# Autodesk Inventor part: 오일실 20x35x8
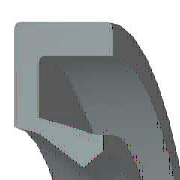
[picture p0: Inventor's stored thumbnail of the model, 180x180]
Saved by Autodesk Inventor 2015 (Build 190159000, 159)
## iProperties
IsCustomPart: 1
Created: 2012-02
Part Number: 오일실 20x35x8
Material: 고무
Description: 오일 실 - 비스프링, 조립 GA
Document SubType Name: Modeling
Standard: JIS B 2402
Designer: mdu-01
Standards Organization: JIS
Language: ko-KR
Size Designation: 20 35 8 A
Categories: <MemberInstance><Categories><Category DisplayName="샤프트 부품" InternalName="7f7aeb1f-a693-4053-b835-cee3144e0d98" Mnemonic="SHFT"><Category DisplayName="실링" Intern
Density: 0.93 g/cm^3
Appearance: Rubber-Black
Author: mdu-01
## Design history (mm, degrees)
body "Solid1"
revolve "회전1" stored, may be unused: angle "d27" = 360 deg
fillet "모깎기1" dims "d28" = 0.4 (= 0.05 x b)
sketch "스케치2"
  geometry: L1 (12.464, -6)-(13.214, -8); L2 (11.464, -5.5)-(12.464, -6); L3 (10, -2.2)-(11.464, -5.5); L4 (11.154, -1.2)-(10, -2.2); L5 (14.5, -7)-(11.154, -1.2); L6 (14.5, -0.4)-(14.5, -7); L7 (16, -0.4)-(14.5, -0.4); L8 (16, 0)-(16, -0.4); L9 (17.5, 0)-(16, 0); L10 (17.5, -8)-(17.5, 0); L11 (13.214, -8)-(17.5, -8); L12 (0, -9.6)-(0, 1.6) reference; L13 (28, 0)-(14, 0) reference
  constraints: 22 end point, 3 horizontal, 3 vertical
  dimensions: "d2" = 8 distance of L10.start L9.start (= b); "d4" = 1.5 distance of L9.start L8.start (= 0.1 x dd - 0.1 x Diam); "d6" = 0.4 distance of L8.start L7.start (= 0.05 x b); "d8" = 1.15385 horizontal distance of L4.start L3.start (= 0.0769231 x dd - 0.0769231 x Diam); "d10" = 1 vertical distance of L5.start L10.start (= 0.125 x b); "d12" = 1.5 distance of L7.start L6.start (= 0.1 x dd - 0.1 x Diam); "d14" = 0.8 vertical distance of L4.start L6.start (= 0.1 x b); "d16" = 4.28571 distance of L1.end L10.start (= 0.285714 x dd - 0.285714 x Diam); "d18" = 0.75 horizontal distance of L1.start L1.end (= 0.05 x dd - 0.05 x Diam); "d20" = 1 vertical distance of L4.start L3.start (= 0.125 x b); "d22" = 2 vertical distance of L1.start L1.end (= 0.25 x b); "d24" = 1 horizontal distance of L2.start L1.start (= 0.0666667 x dd - 0.0666667 x Diam); "d26" = 0.5 vertical distance of L2.start L1.start (= 0.0625 x b); "d29" = 0 distance between parallel lines of L13 L9; "d30" = 10 distance from line of L3.start L12 (= 0.5 x Diam); "d31" = 17.5 distance between parallel lines of L12 L10 (= 0.5 x dd)
other parameters: "dd" = 35 [user parameter; used in 7 equation terms], "b" = 8 [user parameter; used in 8 equation terms], "d1" = 8 (derived), "d3" = 2 (derived), "d5" = 0.4 (derived), "d7" = 1.53846 (derived), "d9" = 1 (derived), "d11" = 2 (derived), "d13" = 0.8 (derived), "d15" = 5.71429 (derived), "d17" = 1 (derived), "d19" = 1 (derived), "d21" = 2 (derived), "d23" = 1.33333 (derived), "d25" = 0.5 (derived), "d32" = 0
